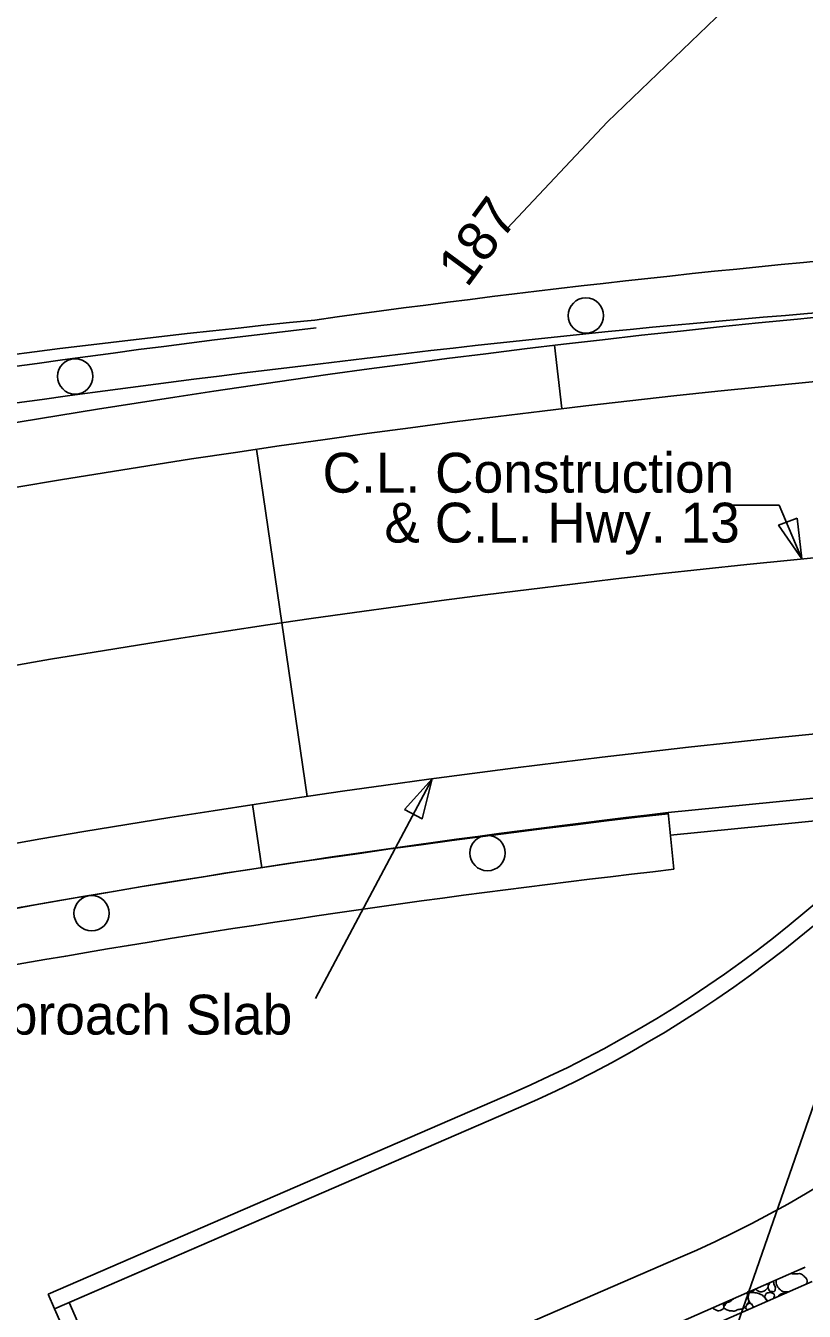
# Model space of a CAD drawing. Extents: x 1385284 to 1385995, y 1975154 to 1975620.
# Drawn here: x 1385397.4 to 1385446.2, y 1975439 to 1975519.6 of the extents above; entities that cross this region are included whole.
import ezdxf

# ---------------------------------------------------------------- set-up
doc = ezdxf.new("R2010")
doc.units = 0
for name, color, linetype in [('B-Super-Deck', 7, 'Continuous'), ('Default', 7, 'Continuous'), ('DTM_CONTOURS_MINOR', 7, 'Continuous'), ('R_Guardrail', 7, 'Continuous'), ('R_Horz Alg', 7, 'Continuous'), ('R_Proposed Const Limits', 7, 'Continuous'), ('R_Proposed Road', 7, 'Continuous'), ('R_Shld', 7, 'Continuous')]:
    doc.layers.add(name, color=color, linetype=linetype)

msp = doc.modelspace()

# ---------------------------------------------------------------- linework, layer by layer
at = {"layer": 'B-Super-Deck'}
for p, q in [((1385437.707, 1975470.297), (1385447.659, 1975471.279)), ((1385437.83, 1975469.053), (1385437.707, 1975470.297)), ((1385437.846, 1975468.888), (1385447.798, 1975469.869))]:
    msp.add_line(p, q, dxfattribs=at)
at = {"layer": 'Default'}
for p, q in [((1385444.681, 1975489.569), (1385441.358, 1975489.569)), ((1385446.095, 1975486.198), (1385444.681, 1975489.569)), ((1385459.101, 1975487.359), (1385417.983, 1975368.797)), ((1385415.574, 1975458.645), (1385422.899, 1975472.414)), ((1385398.824, 1975440.109), (1385427.921, 1975452.706)), ((1385399.221, 1975439.191), (1385428.318, 1975451.788)), ((1385428.318, 1975451.788), (1385399.221, 1975439.191)), ((1385428.318, 1975451.788), (1385400.139, 1975439.588)), ((1385446.305, 1975441.784), (1385405.773, 1975424.049)), ((1385406.173, 1975423.133), (1385446.745, 1975440.885)), ((1385399.221, 1975439.191), (1385398.824, 1975440.109)), ((1385400.139, 1975439.588), (1385406.692, 1975424.452)), ((1385405.776, 1975424.051), (1385399.221, 1975439.191))]:
    msp.add_line(p, q, dxfattribs=at)
for points in [[(1385445.81, 1975488.759), (1385446.095, 1975486.198), (1385444.638, 1975488.323)], [(1385421.173, 1975470.5), (1385422.899, 1975472.414), (1385422.277, 1975469.913)]]:
    msp.add_lwpolyline(points, close=True, dxfattribs=at)
for radius in [75, 76]:
    msp.add_arc((1385398.122, 1975521.532), radius, 293.41039, 324.56338, dxfattribs=at)
for points in [[(1385446.214, 1975441.744), (1385446.193, 1975441.73), (1385446.126, 1975441.699), (1385446.058, 1975441.673), (1385446.014, 1975441.657)], [(1385444.276, 1975440.897), (1385444.29, 1975440.89), (1385444.354, 1975440.858), (1385444.325, 1975440.754), (1385444.387, 1975440.628), (1385444.469, 1975440.492), (1385444.406, 1975440.389), (1385444.424, 1975440.358)], [(1385445.025, 1975440.257), (1385444.957, 1975440.223), (1385444.734, 1975440.361), (1385444.541, 1975440.584), (1385444.456, 1975440.865), (1385444.483, 1975440.987)], [(1385445.414, 1975441.394), (1385445.525, 1975441.386), (1385445.72, 1975441.346), (1385446.029, 1975441.429), (1385446.232, 1975441.223), (1385446.454, 1975441.036), (1385446.422, 1975440.816), (1385446.373, 1975440.722)], [(1385442.61, 1975440.168), (1385442.628, 1975440.159), (1385442.724, 1975440.069), (1385442.719, 1975439.875), (1385442.805, 1975439.564), (1385442.591, 1975439.356), (1385442.369, 1975439.134), (1385442.093, 1975439.167), (1385441.856, 1975438.991), (1385441.691, 1975439.071), (1385441.612, 1975439.05)], [(1385443.08, 1975440.373), (1385443.083, 1975440.356), (1385443.153, 1975440.249), (1385442.494, 1975440.262), (1385442.88, 1975440.251), (1385442.872, 1975440.253)], [(1385443.1, 1975439.29), (1385443.097, 1975439.294), (1385443.013, 1975439.378), (1385442.859, 1975439.537), (1385442.701, 1975439.778), (1385442.733, 1975440.004), (1385442.804, 1975440.246), (1385443.033, 1975440.193), (1385443.303, 1975440.199), (1385443.592, 1975440.054), (1385443.803, 1975439.879), (1385443.897, 1975439.718), (1385443.926, 1975439.651)], [(1385442.838, 1975440.253), (1385442.83, 1975440.253), (1385442.821, 1975440.254), (1385442.813, 1975440.256)], [(1385443.52, 1975440.253), (1385443.449, 1975440.25), (1385443.318, 1975440.31), (1385443.218, 1975440.385), (1385443.181, 1975440.417)], [(1385443.962, 1975440.759), (1385443.966, 1975440.745), (1385443.994, 1975440.667), (1385443.959, 1975440.469), (1385443.773, 1975440.297), (1385443.605, 1975440.253), (1385443.52, 1975440.253)], [(1385443.949, 1975439.662), (1385443.922, 1975439.685), (1385443.836, 1975439.781), (1385443.76, 1975439.91), (1385443.811, 1975440.13), (1385443.975, 1975440.203), (1385444.202, 1975440.21), (1385444.392, 1975440.085), (1385444.371, 1975439.913), (1385444.33, 1975439.842), (1385444.317, 1975439.823)], [(1385444.424, 1975440.358), (1385444.414, 1975440.333), (1385444.366, 1975440.243), (1385444.243, 1975440.258), (1385444.065, 1975440.277), (1385444.027, 1975440.393), (1385443.953, 1975440.502), (1385443.992, 1975440.666), (1385444.074, 1975440.765), (1385444.123, 1975440.822), (1385444.136, 1975440.835)], [(1385444.091, 1975440.815), (1385444.084, 1975440.807), (1385444.074, 1975440.803), (1385444.062, 1975440.803)], [(1385444.56, 1975439.929), (1385444.654, 1975440.046), (1385444.866, 1975440.17), (1385445.097, 1975440.202), (1385445.185, 1975440.203)], [(1385445.318, 1975440.261), (1385445.293, 1975440.257), (1385445.195, 1975440.248), (1385445.097, 1975440.254), (1385445.025, 1975440.257)], [(1385440.888, 1975439.05), (1385440.816, 1975439.061), (1385440.672, 1975439.13), (1385440.543, 1975439.173), (1385440.489, 1975439.236), (1385440.487, 1975439.239)], [(1385441.164, 1975439.535), (1385441.168, 1975439.517), (1385441.188, 1975439.418), (1385441.224, 1975439.2), (1385441.039, 1975439.123), (1385440.936, 1975439.075), (1385440.888, 1975439.05)], [(1385441.327, 1975439.504), (1385441.289, 1975439.504), (1385441.233, 1975439.503), (1385441.19, 1975439.532), (1385441.18, 1975439.542)], [(1385441.612, 1975439.05), (1385441.54, 1975439.046), (1385441.405, 1975439.126), (1385441.145, 1975439.215), (1385441.259, 1975439.384), (1385441.338, 1975439.57), (1385441.563, 1975439.615), (1385441.713, 1975439.731), (1385441.784, 1975439.798), (1385441.798, 1975439.812)], [(1385441.431, 1975439.651), (1385441.444, 1975439.628), (1385441.422, 1975439.575), (1385441.36, 1975439.534), (1385441.327, 1975439.504)], [(1385441.754, 1975439.77), (1385441.711, 1975439.757), (1385441.668, 1975439.747), (1385441.624, 1975439.736)], [(1385441.806, 1975439.816), (1385441.792, 1975439.798), (1385441.775, 1975439.782), (1385441.754, 1975439.77)], [(1385442.7, 1975439.115), (1385442.697, 1975439.117), (1385442.649, 1975439.153), (1385442.532, 1975439.215), (1385442.641, 1975439.401), (1385442.689, 1975439.565), (1385442.87, 1975439.539), (1385442.988, 1975439.436), (1385443.027, 1975439.325), (1385443.05, 1975439.268)]]:
    msp.add_open_spline(points, degree=3, dxfattribs=at)
at = {"layer": 'DTM_CONTOURS_MINOR'}
msp.add_lwpolyline([(1385519.816, 1975518.527), (1385513.167, 1975531.095), (1385503.103, 1975535.092), (1385493.819, 1975536.129), (1385487.034, 1975541.44), (1385476.692, 1975537.174), (1385462.514, 1975531.326), (1385459.65, 1975533.856), (1385457.485, 1975537.268), (1385444.649, 1975523.958), (1385443.539, 1975522.941), (1385443.305, 1975522.664), (1385433.898, 1975513.612), (1385427.6, 1975506.926)], dxfattribs=at)
at = {"layer": 'R_Guardrail'}
for centre in [(1385432.546, 1975501.46), (1385400.508, 1975497.646), (1385426.376, 1975467.761), (1385401.541, 1975463.985)]:
    msp.add_circle(centre, 1.109, dxfattribs=at)
for centre, radius, start, end in [((1385504.568, 1974790.969), 712.994, 93.552431, 97.144548), ((1385496.707, 1974793.551), 711.773, 96.540619, 100.675006), ((1385496.707, 1974793.551), 709.494, 96.540619, 100.675006), ((1385515.914, 1974795.319), 679.494, 96.609178, 100.218679)]:
    msp.add_arc(centre, radius, start, end, dxfattribs=at)
at = {"layer": 'R_Horz Alg'}
msp.add_arc((1385514.357, 1974795.066), 694.494, 77.498258, 106.635112, dxfattribs=at)
at = {"layer": 'R_Proposed Const Limits'}
msp.add_lwpolyline([(1385315.54, 1975398.935), (1385369.259, 1975412.439), (1385438.344, 1975442.349)], dxfattribs=at)
msp.add_arc((1385408.545, 1975511.176), 75, 293.41039, 324.56338, dxfattribs=at)
at = {"layer": 'R_Proposed Road'}
for p, q in [((1385430.574, 1975499.596), (1385431.046, 1975495.624)), ((1385415.069, 1975471.31), (1385411.873, 1975493.077)), ((1385412.225, 1975466.841), (1385411.623, 1975470.796))]:
    msp.add_line(p, q, dxfattribs=at)
for radius, end in [(705.494, 106.368381), (683.494, 106.910819)]:
    msp.add_arc((1385514.357, 1974795.066), radius, 77.498258, end, dxfattribs=at)
at = {"layer": 'R_Shld'}
msp.add_line((1385438.058, 1975466.741), (1385437.707, 1975470.297), dxfattribs=at)
for centre, radius, start, end in [((1385514.357, 1974795.066), 712.994, 94.35844, 97.966039), ((1385514.357, 1974795.066), 709.494, 93.554346, 106.273527), ((1385487.076, 1974789.909), 714.859, 95.742746, 99.871271), ((1385514.357, 1974795.066), 679.494, 96.476368, 107.013391), ((1385514.357, 1974795.066), 675.994, 96.480734, 100.084957)]:
    msp.add_arc(centre, radius, start, end, dxfattribs=at)

# ---------------------------------------------------------------- texts
at = {"layer": 'Default'}
msp.add_text('187', height=2.5, rotation=53.64518, dxfattribs=at).set_placement((1385425.095, 1975503.151))
for s, p in [('C.L. Construction', (1385416.026, 1975490.357)), ('& C.L. Hwy. 13', (1385419.908, 1975487.227)), ('Approach Slab', (1385392.196, 1975456.378))]:
    msp.add_text(s, height=2.49999, dxfattribs=at).set_placement(p)

doc.saveas('drawing.dxf')
